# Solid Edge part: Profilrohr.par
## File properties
Username: bmolnar
Dokumentum tartalom típus: 0
Author: bmolnar
Last saved by: bmolnar
Revision: 91
Sűrűség: 0,000 kg/m^3
Pontosság: 0,990
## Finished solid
Body 1: solid body, 63 faces, 178 edges, 112 vertices.
  Faces by surface: cylinder 33, plane 30
  Edges by curve: line 112, circle 66
Bounding box of the edges (mm): 36.000 x 138.400 x 36.000, from (-18, -129.15, -18) to (18, 9.25, 18).
Cylindrical faces by radius (mm): R0.2 x12, R0.5 x12, R3.775 x4, R4.5 x4, R10 x1
Planar faces by outward normal: +x 7, +y 1, +z 7, -x 7, -y 1, -z 7
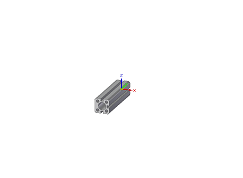
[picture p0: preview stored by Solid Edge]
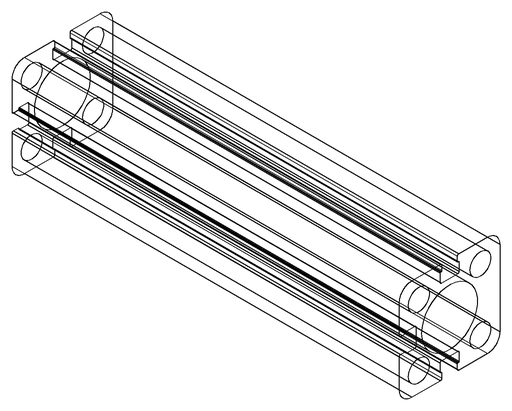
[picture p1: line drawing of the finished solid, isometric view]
